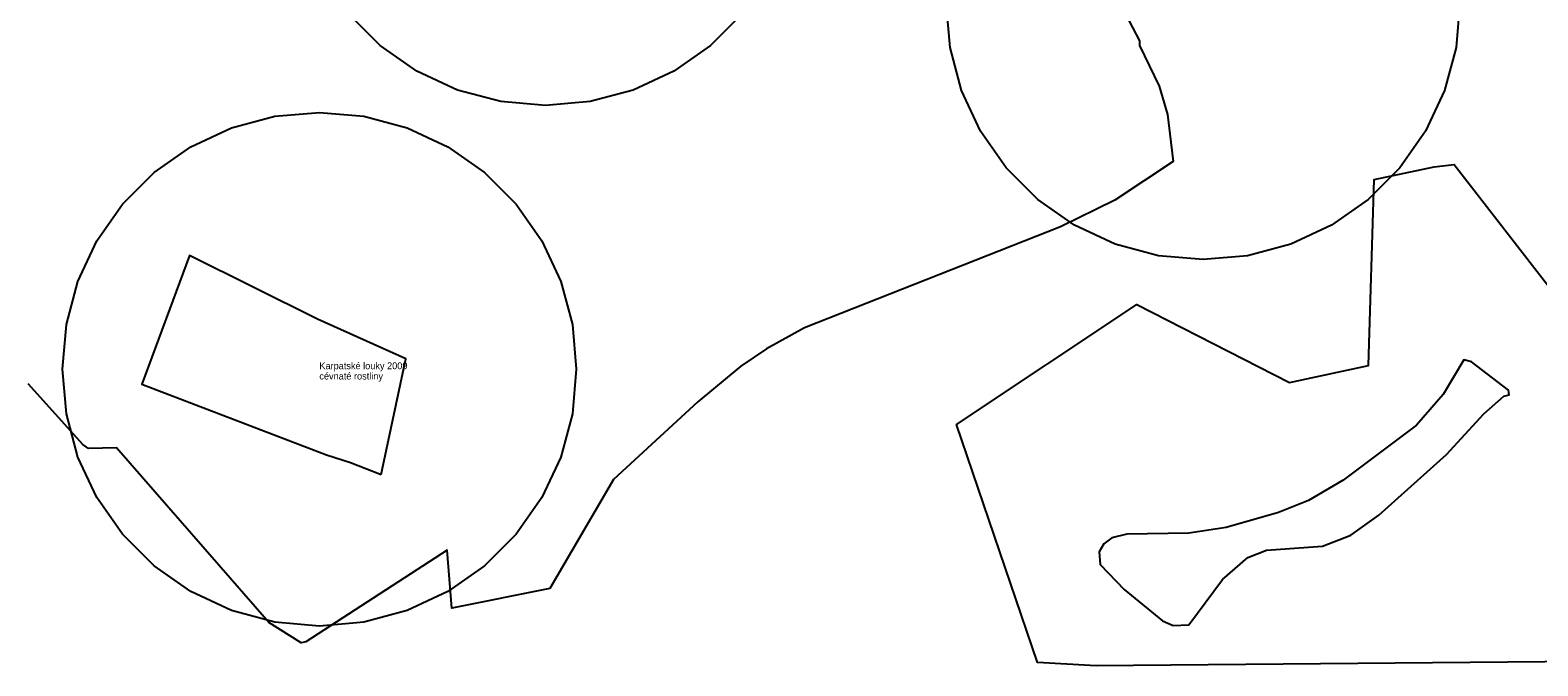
# Model space of a CAD drawing. Extents: x -477403 to -465463, y -1159182 to -1149227.
# Drawn here: x -473839.4 to -473399.3, y -1157019.6 to -1156834 of the extents above; entities that cross this region are included whole.
import ezdxf

# ---------------------------------------------------------------- set-up
doc = ezdxf.new("R2010")
doc.units = 0
for name, color, linetype in [('Vrstva 1', 7, 'Continuous'), ('Vrstva 10_stav', 7, 'Continuous'), ('Vrstva 2', 7, 'Continuous')]:
    doc.layers.add(name, color=color, linetype=linetype)

msp = doc.modelspace()

# ---------------------------------------------------------------- linework, layer by layer
at = {"layer": 'Vrstva 10_stav'}
for points in [[(-473525.656, -1156817.75), (-473515.562, -1156837.125), (-473515.562, -1156838.5), (-473509.812, -1156850.375), (-473507.344, -1156858.625), (-473505.688, -1156872.375), (-473522.781, -1156883.625), (-473538.656, -1156891.375), (-473613.312, -1156920.875), (-473624.406, -1156927), (-473631.906, -1156932.125), (-473644.5, -1156942.5), (-473669.125, -1156965.25), (-473687.719, -1156997), (-473716.281, -1157002.75), (-473717.656, -1156985.875), (-473758.969, -1157012.625), (-473760.312, -1157012.875), (-473769.75, -1157007), (-473814.188, -1156956), (-473822.406, -1156956.125), (-473824.062, -1156955), (-473840.062, -1156937.25)], [(-473422, -1156826), (-473423.139, -1156839.024), (-473426.523, -1156851.652), (-473432.048, -1156863.5), (-473439.547, -1156874.209), (-473448.791, -1156883.453), (-473459.5, -1156890.952), (-473471.348, -1156896.477), (-473483.976, -1156899.861), (-473497, -1156901), (-473510.024, -1156899.861), (-473522.652, -1156896.477), (-473534.5, -1156890.952), (-473545.209, -1156883.453), (-473554.453, -1156874.209), (-473561.952, -1156863.5), (-473567.477, -1156851.652), (-473570.861, -1156839.024), (-473572, -1156826)], [(-473631.547, -1156829.209), (-473640.791, -1156838.453), (-473651.5, -1156845.952), (-473663.348, -1156851.477), (-473675.976, -1156854.861), (-473689, -1156856), (-473702.024, -1156854.861), (-473714.652, -1156851.477), (-473726.5, -1156845.952), (-473737.209, -1156838.453), (-473746.453, -1156829.209)], [(-473386.312, -1157018.375), (-473528.25, -1157019.625), (-473545.344, -1157018.625), (-473568.969, -1156949.125), (-473516.375, -1156914.125), (-473471.781, -1156936.875), (-473448.688, -1156931.875), (-473447.031, -1156877.625), (-473429.531, -1156873.875), (-473423.656, -1156873.25), (-473387.719, -1156919.625)]]:
    msp.add_lwpolyline(points, dxfattribs=at)
for points in [[(-473680, -1156933), (-473681.139, -1156946.024), (-473684.523, -1156958.652), (-473690.048, -1156970.5), (-473697.547, -1156981.209), (-473706.791, -1156990.453), (-473717.5, -1156997.952), (-473729.348, -1157003.477), (-473741.976, -1157006.861), (-473755, -1157008), (-473768.024, -1157006.861), (-473780.652, -1157003.477), (-473792.5, -1156997.952), (-473803.209, -1156990.453), (-473812.453, -1156981.209), (-473819.952, -1156970.5), (-473825.477, -1156958.652), (-473828.861, -1156946.024), (-473830, -1156933), (-473828.861, -1156919.976), (-473825.477, -1156907.348), (-473819.952, -1156895.5), (-473812.453, -1156884.791), (-473803.209, -1156875.547), (-473792.5, -1156868.048), (-473780.652, -1156862.523), (-473768.024, -1156859.139), (-473755, -1156858), (-473741.976, -1156859.139), (-473729.348, -1156862.523), (-473717.5, -1156868.048), (-473706.791, -1156875.547), (-473697.547, -1156884.791), (-473690.048, -1156895.5), (-473684.523, -1156907.348), (-473681.139, -1156919.976)], [(-473736.938, -1156963.75), (-473729.75, -1156930), (-473755.531, -1156918.375), (-473792.875, -1156899.75), (-473806.812, -1156937.375), (-473752.875, -1156958), (-473745.938, -1156960.25)], [(-473505.688, -1157007.875), (-473501.188, -1157007.625), (-473491.344, -1156994.375), (-473483.969, -1156988), (-473478.5, -1156985.875), (-473462.094, -1156984.625), (-473453.875, -1156981.5), (-473445.656, -1156975.625), (-473425.969, -1156957.875), (-473415.031, -1156946), (-473409.156, -1156940.875), (-473407.656, -1156940.5), (-473407.781, -1156939.125), (-473418.594, -1156930.875), (-473420.906, -1156930.25), (-473426.938, -1156940.375), (-473434.719, -1156949.375), (-473456.062, -1156965.375), (-473466.188, -1156971.375), (-473474.938, -1156974.875), (-473490.25, -1156979.25), (-473501.188, -1156980.875), (-473519.25, -1156981.125), (-473523.625, -1156982.25), (-473525.938, -1156984), (-473527.312, -1156986.375), (-473527.031, -1156990), (-473520.062, -1156997.375), (-473508.844, -1157006.5)]]:
    msp.add_lwpolyline(points, close=True, dxfattribs=at)

# ---------------------------------------------------------------- texts
at = {"layer": 'Vrstva 1'}
msp.add_text('cévnaté rostliny', height=2, dxfattribs=at).set_placement((-473755, -1156936))
msp.add_text('cévnaté rostliny', height=2, dxfattribs=at).set_placement((-473755, -1156936))
at = {"layer": 'Vrstva 2'}
msp.add_text('Karpatské louky 2009', height=2, dxfattribs=at).set_placement((-473755, -1156933))
msp.add_text('Karpatské louky 2009', height=2, dxfattribs=at).set_placement((-473755, -1156933))

doc.saveas('drawing.dxf')
